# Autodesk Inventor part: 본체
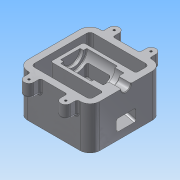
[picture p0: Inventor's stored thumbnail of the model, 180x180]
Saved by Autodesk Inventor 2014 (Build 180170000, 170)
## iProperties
Created: 2018-01
Part Number: 본체
Material: 알루미늄 6061
Document SubType Name: Modeling
Designer: Administrator
Density: 2.71 g/cm^3
Appearance: 알루미늄 - 평지
Mass: 998.935 g
Surface Area: 834.397 cm^2
Volume: 368.611 cm^3
Author: Administrator
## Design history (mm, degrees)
sketch "스케치1"
  geometry: L1 (55, -55)-(-55, -55); L2 (-55, -55)-(-55, 55); L3 (-55, 55)-(55, 55); L4 (55, 55)-(55, -55); L5 (55, -55)-(-55, 55); L6 (-55, -55)-(55, 55); L7 (45, -45)-(-45, -45); L8 (-45, -45)-(-45, 45); L9 (-45, 45)-(45, 45); L10 (45, 45)-(45, -45); L11 (45, -45)-(-45, 45); L12 (-45, -45)-(45, 45); 2 further points
  constraints: 24 end point, 6 midpoint, 4 parallel, 2 horizontal, 2 perpendicular, 1 point on line
  dimensions: "d0" = 110 distance of L2.end L3.end; "d1" = 110 distance of L1.end L2.end; "d2" = 90 distance of L8.end L9.end
extrude "돌출1" new body sketch "스케치1" distance "d3" = 65; taper "d4" = 0 deg
fillet "모깎기1" dims "d5" = 15
fillet "모깎기2" dims "d6" = 5
sketch "스케치2"
  geometry: L1 (-55, 40)-(-55, -40) reference; L2 (55, -40)-(55, 40) reference; L3 (40, 55)-(-40, 55) reference; L4 (-55, 40)-(-55, 94.113); L5 (-55, 55)-(55, 55); L6 (-55, 65)-(55, 65); L7 (-28, 40)-(-28, 94.113); L8 (-35.5, 65)-(-35.5, 55); L9 (-20.5, 65)-(-20.5, 55); L10 (-55, 0)-(55, 0); L11 (55, 40)-(55, 103.462); L12 (28, 40)-(28, 103.462); L13 (20.5, 65)-(20.5, 55); L14 (35.5, 65)-(35.5, 55); A1 r 15 centre (-40, 40) between (-40, 55) and (-55, 40) reference; A2 r 15 centre (40, 40) between (55, 40) and (40, 55) reference; A3 r 7.5 centre (-28, 65) between (-35.5, 65) and (-20.5, 65); A4 r 7.5 centre (28, 65) between (20.5, 65) and (35.5, 65); 1 further point
  constraints: 22 end point, 11 point on line, 7 perpendicular, 6 tangent, 4 point on circle, 3 parallel, 2 centre point, 2 midpoint
  dimensions: "d7" = 10 distance between parallel lines of L6 L5; "d8" = 27 distance between parallel lines of L7 L4; "d9" = 15 diameter of A3; "d10" = 27 distance between parallel lines of L11 L12; "d11" = 15 diameter of A4
extrude "돌출2" join sketch "스케치2" distance "d12" = 20; taper "d13" = 0 deg
node "작업 평면1"
sketch "스케치3"
  geometry: L1 (-55, 0)-(-55, 65) reference; L2 (55, 65)-(55, 0) reference; L3 (-40, 65)-(40, 65) reference; L4 (40, 0)-(-40, 0) reference; L5 (-55, 65)-(35, 65); L6 (35, 65)-(35, 30); L7 (35, 30)-(-55, 5.885); L8 (-55, 5.885)-(-55, 65); 1 further point
  constraints: 8 end point, 2 point on line, 1 collinear, 1 perpendicular
  dimensions: "d15" = 90 distance of L1.end L5.end; "d16" = 30 distance from line of L6.end L4; "d17" = 105 deg angle of L6 L7
extrude "돌출3" join sketch "스케치3" stored distance "d18" = 50; taper "d19" = 0 deg
sketch "스케치4"
  geometry: L1 (-55, 0)-(-55, 65) reference; L2 (-55, 65)-(-40, 65) reference; L3 (-55, 65)-(54.184, 65); L4 (-55, 65)-(-55, 57.5); L5 (-36, 57.5)-(-36, 49); L6 (-36, 49)-(-22, 49); L7 (-22, 49)-(-22, 45); L8 (-22, 45)-(25, 45); L9 (25, 45)-(25, 50); L10 (25, 50)-(30, 50); L11 (30, 50)-(30, 65); L12 (-55, 57.5)-(-36, 57.5); 1 further point
  constraints: 20 end point, 5 parallel, 3 perpendicular, 3 point on line
  dimensions: "d21" = 32 diameter of L6 L3; "d22" = 7.5 distance between parallel lines of L2 L12; "d23" = 40 diameter of L8 L3; "d24" = 19 distance of L4.end L5.start; "d25" = 14 distance of L5.end L6.end; "d26" = 47 distance of L7.end L8.end; "d27" = 5 distance of L9.end L10.end; "d28" = 30 diameter of L10 L3
revolve "회전1" sketch "스케치4" stored, may be unused: angle "d29" = 90 deg
sketch "스케치5"
  geometry: L1 (-55, 0)-(-55, 65) reference; L2 (35, 65)-(35, 30) reference; L3 (35, 30)-(-45, 8.564); L4 (-55, 11.061)-(20, 31.157); L5 (-22, 45)-(25, 45) reference; L6 (25, 45)-(25, 65) reference; L7 (30, 50)-(30, 65) reference; L8 (-17, 45)-(-17, 39.243); L9 (-17, 39.243)-(-55, 29.061); L10 (-55, 29.061)-(-55, 11.061); L11 (20, 31.157)-(20, 55); L12 (-17, 45)-(-17, 55); L13 (-17, 60.906)-(20, 60.906); L14 (20, 60.906)-(20, 55); L15 (-17, 60.906)-(-17, 55); L16 (-22, 45)-(-22, 65) reference; 2 further points
  constraints: 20 end point, 5 parallel, 2 perpendicular, 2 point on line, 1 midpoint
  dimensions: "d30" = 5 distance between parallel lines of L3 L4; "d32" = 37 distance of L13.start L13.end; "d42" = 18 distance of L4.start L9.end; "d43" = 5 distance between parallel lines of L12 L16
extrude "돌출4" cut sketch "스케치5" stored distance "d33" = 30; taper "d34" = 0 deg
sketch "스케치6"
  geometry: A1 r 7.5 centre (28, 65) between (35.5, 65) and (20.5, 65) reference; A2 r 7.5 centre (-28, 65) between (-20.5, 65) and (-35.5, 65) reference; A3 r 7.5 centre (-28, -65) between (-35.5, -65) and (-20.5, -65) reference; A4 r 7.5 centre (28, -65) between (20.5, -65) and (35.5, -65) reference; 5 further points
  constraints: 4 coincident
hole "구멍1" sketch "스케치6" at (-28, 65), (28, 65), (28, -65), (-28, -65) diameter "d35" = 3.242; stored, may be unused: countersink angle "d39" = 90 deg, drill point angle "d41" = 118 deg; dims "d36" = 9, "d37" = 4, "d38" = 2, "d40" = 11
sketch "스케치7"
  geometry: L1 (0, 0)-(80, 0) reference; L2 (95.225, 0)-(40.225, 0); L3 (40.225, 0)-(40.225, -20); 2 further points
  constraints: 4 end point, 1 coincident, 1 perpendicular, 1 point on line, 1 other
  dimensions: "d45" = 55 distance of L2.start L2.end; "d46" = 20 distance of L2.end L3.end
feature "엠보싱1" sketch "스케치7" dims "d0" = 110, "d1" = 110, "d2" = 90, "d47" = 0.5, "d48" = 0
fillet "모깎기3" dims "d49" = 3
fillet "모깎기4" dims "d50" = 3
chamfer "모따기1" distance "d51" = 1; stored, may be unused: second distance "d52" = 2, angle "d53" = 45 deg
fillet "모깎기5" dims "d54" = 3
fillet "모깎기6" dims "d55" = 3
fillet "모깎기7" dims "d56" = 3
fillet "모깎기8" dims "d57" = 3
fillet "모깎기9" dims "d58" = 1
chamfer "모따기2" distance "d59" = 1; stored, may be unused: second distance "d60" = 2, angle "d61" = 45 deg
node "솔리드1"
mirror "대칭1"
other parameters: "d14" = 0
